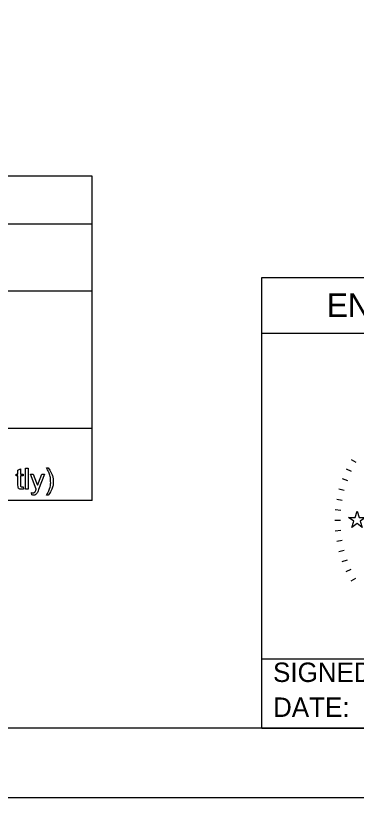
# Model space of a CAD drawing. Extents: x -5.6 to 34, y 0 to 22.
# Drawn here: x 6.68 to 9.13, y 0 to 5.64 of the extents above; entities that cross this region are included whole.
import ezdxf

# ---------------------------------------------------------------- set-up
doc = ezdxf.new("R2010")
doc.units = 0
for name, color, linetype in [('Default', 7, 'Continuous'), ('SH_Border', 7, 'Continuous'), ('SH_Cut_Line', 7, 'Continuous'), ('SH_Data', 7, 'Continuous'), ('SH_Text', 7, 'Continuous')]:
    doc.layers.add(name, color=color, linetype=linetype)

msp = doc.modelspace()

# ---------------------------------------------------------------- linework, layer by layer
at = {"layer": 'Default'}
msp.add_lwpolyline([(9.0736, 2.02), (9.1205, 2.02), (9.135, 2.0645), (9.1495, 2.02), (9.1964, 2.02), (9.1585, 1.9924), (9.173, 1.9478), (9.135, 1.9754), (9.097, 1.9478), (9.1115, 1.9924)], close=True, dxfattribs=at)
at = {"layer": 'SH_Border'}
msp.add_lwpolyline([(1.5, 21.5), (33.5, 21.5), (33.5, 0.5), (1.5, 0.5)], close=True, dxfattribs=at)
at = {"layer": 'SH_Cut_Line'}
msp.add_lwpolyline([(0, 0), (34, 0), (34, 22), (0, 22)], close=True, dxfattribs=at)
at = {"layer": 'SH_Data'}
for p, q in [((7.2275, 4.4803), (2.9775, 4.4803)), ((7.2275, 2.1428), (7.2275, 4.4803)), ((2.9775, 4.1387), (7.2275, 4.1387)), ((8.45, 0.5), (8.45, 3.75)), ((8.45, 3.75), (11.25, 3.75)), ((8.45, 0.5), (8.45, 3.75)), ((8.45, 3.75), (11.25, 3.75)), ((2.9775, 3.6553), (7.2275, 3.6553)), ((8.45, 3.35), (11.25, 3.35)), ((7.2275, 2.6607), (2.9775, 2.6607)), ((9.0922, 2.4375), (9.1269, 2.4175)), ((9.057, 2.3698), (9.0932, 2.3529)), ((9.0278, 2.2993), (9.0654, 2.2856)), ((9.0048, 2.2265), (9.0435, 2.2161)), ((8.9883, 2.1519), (9.0277, 2.145)), ((7.2275, 2.1428), (2.9775, 2.1428)), ((8.9783, 2.0763), (9.0182, 2.0728)), ((8.975, 2), (9.015, 2)), ((8.9783, 1.9237), (9.0182, 1.9272)), ((8.9883, 1.8481), (9.0277, 1.855)), ((9.0048, 1.7735), (9.0435, 1.7839)), ((9.0278, 1.7007), (9.0654, 1.7144)), ((9.057, 1.6302), (9.0932, 1.6471)), ((9.0922, 1.5625), (9.1269, 1.5825)), ((8.45, 0.5), (11.25, 0.5))]:
    msp.add_line(p, q, dxfattribs=at)
msp.add_lwpolyline([(8.45, 0.5), (8.45, 1), (11.25, 1), (11.25, 0.5)], close=True, dxfattribs=at)
at = {"layer": 'SH_Text'}
for points in [[(6.692, 2.2558), (6.692, 2.3185), (6.6784, 2.3185), (6.6784, 2.3328), (6.692, 2.3328), (6.692, 2.3597), (6.7105, 2.3708), (6.7105, 2.3328), (6.7289, 2.3328), (6.7289, 2.3185), (6.7105, 2.3185), (6.7105, 2.2547)], [(6.7465, 2.2239), (6.7465, 2.3741), (6.7649, 2.3741), (6.7649, 2.2239), (6.7465, 2.2239)], [(6.8974, 2.3766), (6.9105, 2.3766)], [(6.8243, 2.2238), (6.783, 2.3328), (6.8029, 2.3328), (6.8255, 2.2699)], [(6.841, 2.2693), (6.8643, 2.3328), (6.8827, 2.3328), (6.8414, 2.222)], [(6.7289, 2.2404), (6.7315, 2.2241)], [(6.7928, 2.1821), (6.7907, 2.1995)], [(6.9105, 2.1798), (6.8974, 2.1798)]]:
    msp.add_lwpolyline(points, dxfattribs=at)
for points in [[(6.8974, 2.1798), (6.9279, 2.2289), (6.9279, 2.2782), (6.9279, 2.2974), (6.9235, 2.3164), (6.92, 2.3317), (6.9138, 2.3459), (6.9098, 2.3551), (6.8974, 2.3766)], [(6.9105, 2.3766), (6.9298, 2.3509), (6.939, 2.325), (6.9469, 2.3026), (6.9469, 2.2783), (6.9469, 2.2506), (6.9363, 2.2248), (6.9257, 2.199), (6.9105, 2.1798)], [(6.8255, 2.2699), (6.8299, 2.258), (6.8334, 2.2448), (6.8366, 2.2572), (6.841, 2.2693)], [(6.7315, 2.2241), (6.7238, 2.2224), (6.7176, 2.2224), (6.7076, 2.2224), (6.7021, 2.2256), (6.6965, 2.2288), (6.6943, 2.234), (6.692, 2.2392), (6.692, 2.2558)], [(6.7105, 2.2547), (6.7105, 2.2468), (6.7114, 2.2445), (6.7124, 2.2423), (6.7146, 2.2409), (6.7168, 2.2396), (6.7209, 2.2396), (6.7239, 2.2396), (6.7289, 2.2404)], [(6.7907, 2.1995), (6.7967, 2.1978), (6.8012, 2.1978), (6.8074, 2.1978), (6.811, 2.1999), (6.8147, 2.2019), (6.8171, 2.2056), (6.8188, 2.2084), (6.8227, 2.2193), (6.8232, 2.2209), (6.8243, 2.2238)], [(6.8414, 2.222), (6.8348, 2.2042), (6.8311, 2.1974), (6.8262, 2.1883), (6.8198, 2.1841), (6.8135, 2.1799), (6.8046, 2.1799), (6.7993, 2.1799), (6.7928, 2.1821)]]:
    msp.add_open_spline(points, degree=3, dxfattribs=at)

# ---------------------------------------------------------------- texts
at = {"layer": 'SH_Data'}
msp.add_text("ENGINEER'S SEAL", height=0.17, dxfattribs=at).set_placement((8.9176, 3.465))
at = {"layer": 'SH_Text'}
for s, p in [('SIGNED:', (8.53, 0.8324)), ('DATE:', (8.53, 0.5805))]:
    msp.add_text(s, height=0.14, dxfattribs=at).set_placement(p)

doc.saveas('drawing.dxf')
